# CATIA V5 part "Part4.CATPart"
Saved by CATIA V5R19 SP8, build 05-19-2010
Part number: Rabatteur_Haut
Bounding box of the stored display mesh (mm): x 0 to 0, y -400 to 400, z 60 to 195
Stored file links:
  G:\EU_thinkMotion\CFAO_2010\MMS_groupe1\MMS_groupe1\OK\ppiault\piault\piault_cfao\Part4.CATPart
  D:\Catia\Finaltest.CATProduct
  G:\EU_thinkMotion\CFAO_2010\MMS_groupe1\MMS_groupe1\OK\ppiault\piault\piault_cfao\Part2.CATPart
  G:\EU_thinkMotion\CFAO_2010\MMS_groupe1\MMS_groupe1\OK\ppiault\piault\piault_cfao\Part3.CATPart
  G:\EU_thinkMotion\CFAO_2010\MMS_groupe1\MMS_groupe1\OK\ppiault\piault\piault_cfao\Part1.CATPart
  G:\Catia Projet\CFAO2\Product2.CATProduct
  G:\EU_thinkMotion\CFAO_2010\MMS_groupe1\MMS_groupe1\OK\ppiault\piault\piault_cfao\Part5.CATPart
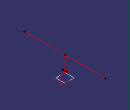
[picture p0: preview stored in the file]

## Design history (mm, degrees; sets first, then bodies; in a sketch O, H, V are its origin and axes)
External parameters (linked from other documents)
  External.DiametreRabatteur = 400 mm
Set1
  Point1: linked copy from another document
  Plane1: linked copy from another document
  Point2: linked copy from another document
Set2
  Line1: type PtDir, RefPoint Point1, Direction Plane1, Start -400 {= -External.DiametreRabatteur}, End 400 {= External.DiametreRabatteur}
  Line2: type PtPt, FirstPoint Point1, SecondPoint Point2
  Line3: type PtDir, RefPoint Point2, Direction Plane1, Start -20, End 20
Body1 (main body)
